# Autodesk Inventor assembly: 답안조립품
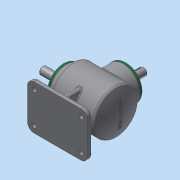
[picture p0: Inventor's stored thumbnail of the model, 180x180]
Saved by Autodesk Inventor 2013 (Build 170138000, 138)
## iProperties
Created: 2016-09
Part Number: 답안조립품
Document SubType Name: Assembly
Designer: dgall
Author: dgall
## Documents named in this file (14)
- C:\Users\dgall\Desktop\460907V1013\답안조립품.iam
- C:\Users\dgall\Desktop\460907V1013\본체.ipt
- C:\Users\dgall\Desktop\460907V1013\M4.ipt
- C:\Users\dgall\Desktop\460907V1013\메인 베벨기어.ipt
- C:\Users\dgall\Desktop\460907V1013\메인 축.ipt
- 메인 축.ipt
- C:\Users\dgall\Desktop\460907V1013\베어링 6203.ipt
- C:\Users\dgall\Desktop\460907V1013\서브 베벨기어.ipt
- C:\Users\dgall\Desktop\460907V1013\서브 축.ipt
- 서브 축.ipt
- C:\Users\dgall\Desktop\460907V1013\오일실 17 32 8.ipt
- C:\Users\dgall\Desktop\460907V1013\커버.ipt
- C:\Users\dgall\Desktop\460907V1013\키 4x4.ipt
- C:\Users\dgall\Desktop\460907V1013\키 5x5.ipt
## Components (8 placed, 1 different names)
1. M4:2
2. M4:3
3. M4:4
4. M4:5
5. M4:1
6. M4:6
7. M4:7
8. M4:8
